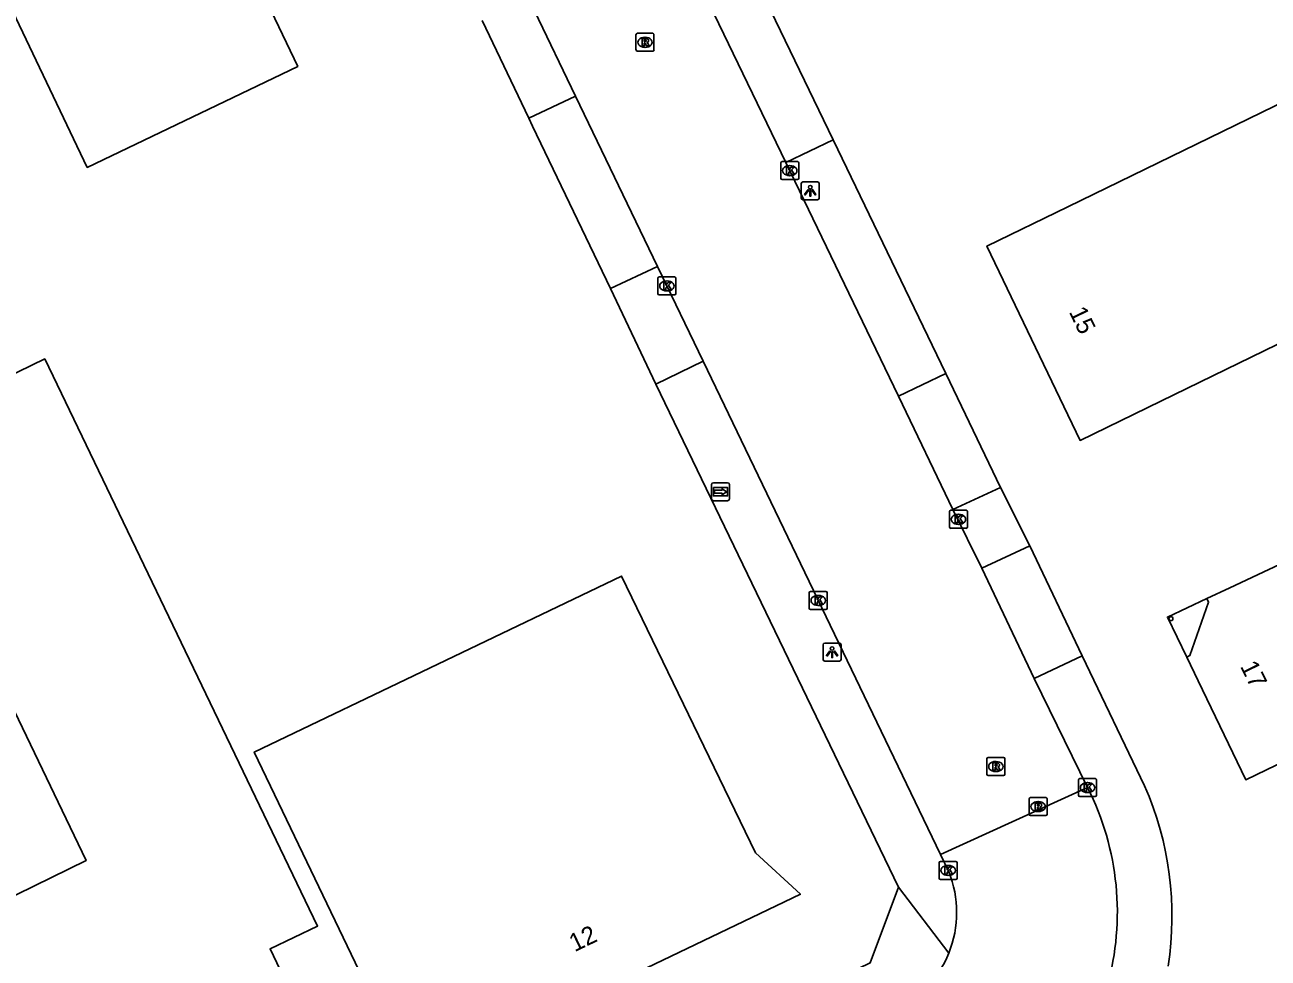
# Model space of a CAD drawing. Extents: x 157692 to 159670, y 381454 to 383289.
# Drawn here: x 158074.3 to 158143.4, y 381697.4 to 381749.2 of the extents above; entities that cross this region are included whole.
import ezdxf

# ---------------------------------------------------------------- set-up
doc = ezdxf.new("R2010")
doc.units = 0
for name, color, linetype in [('IMGEO_Kolk', 7, 'Continuous'), ('IMGEO_Lichtpunt', 7, 'Continuous'), ('IMGEO_Pand', 7, 'Continuous'), ('IMGEO_Pand_nummerreeks', 7, 'Continuous'), ('IMGEO_Pand_overbouw', 7, 'Continuous'), ('IMGEO_Rijbaan_lokaal_gesloten', 7, 'Continuous'), ('IMGEO_Rioolput', 7, 'Continuous'), ('IMGEO_Voetpad_open', 7, 'Continuous'), ('IMGEO_Wegwijzer', 7, 'Continuous')]:
    doc.layers.add(name, color=color, linetype=linetype)

msp = doc.modelspace()

# ---------------------------------------------------------------- linework, layer by layer
at = {"layer": 'IMGEO_Kolk'}
for p, q in [((158116.342, 381740.701), (158116.342, 381741.553)), ((158116.417, 381741.627), (158117.269, 381741.627)), ((158117.343, 381741.553), (158117.343, 381740.701)), ((158116.853, 381740.847), (158116.828, 381740.847)), ((158116.83, 381741.407), (158116.855, 381741.407)), ((158117.269, 381740.627), (158116.417, 381740.627)), ((158109.588, 381735.218), (158110.44, 381735.218)), ((158109.513, 381734.292), (158109.513, 381735.144)), ((158110.001, 381734.998), (158110.026, 381734.998)), ((158110.514, 381735.144), (158110.514, 381734.292)), ((158110.44, 381734.218), (158109.588, 381734.218)), ((158110.024, 381734.438), (158109.999, 381734.438)), ((158125.718, 381721.323), (158125.718, 381722.175)), ((158125.793, 381722.249), (158126.645, 381722.249)), ((158126.719, 381722.175), (158126.719, 381721.323)), ((158126.229, 381721.469), (158126.204, 381721.469)), ((158126.206, 381722.029), (158126.231, 381722.029)), ((158126.645, 381721.249), (158125.793, 381721.249)), ((158117.926, 381716.814), (158117.926, 381717.666)), ((158118.001, 381717.74), (158118.853, 381717.74)), ((158118.414, 381717.52), (158118.439, 381717.52)), ((158118.927, 381717.666), (158118.927, 381716.814)), ((158118.853, 381716.74), (158118.001, 381716.74)), ((158118.437, 381716.96), (158118.412, 381716.96)), ((158132.896, 381706.414), (158132.896, 381707.266)), ((158132.971, 381707.34), (158133.823, 381707.34)), ((158133.384, 381707.12), (158133.409, 381707.12)), ((158133.897, 381707.266), (158133.897, 381706.414)), ((158133.823, 381706.34), (158132.971, 381706.34)), ((158133.407, 381706.56), (158133.382, 381706.56)), ((158125.221, 381702.739), (158126.073, 381702.739)), ((158125.146, 381701.813), (158125.146, 381702.665)), ((158125.634, 381702.519), (158125.659, 381702.519)), ((158126.147, 381702.665), (158126.147, 381701.813)), ((158126.073, 381701.739), (158125.221, 381701.739)), ((158125.657, 381701.959), (158125.632, 381701.959))]:
    msp.add_line(p, q, dxfattribs=at)
for points in [[(158116.342, 381740.701), (158116.342, 381741.553)], [(158116.417, 381741.627), (158117.269, 381741.627)], [(158117.343, 381741.553), (158117.343, 381740.701)], [(158116.663, 381741.327), (158116.786, 381741.327), (158116.786, 381741.176), (158116.916, 381741.327), (158117.08, 381741.327), (158116.934, 381741.176), (158117.087, 381740.927), (158116.935, 381740.927), (158116.85, 381741.091), (158116.786, 381741.024), (158116.786, 381740.927), (158116.663, 381740.927), (158116.663, 381741.327)], [(158117.269, 381740.627), (158116.417, 381740.627)], [(158109.588, 381735.218), (158110.44, 381735.218)], [(158109.513, 381734.292), (158109.513, 381735.144)], [(158109.834, 381734.918), (158109.957, 381734.918), (158109.957, 381734.767), (158110.087, 381734.918), (158110.251, 381734.918), (158110.105, 381734.767), (158110.258, 381734.518), (158110.106, 381734.518), (158110.021, 381734.682), (158109.957, 381734.615), (158109.957, 381734.518), (158109.834, 381734.518), (158109.834, 381734.918)], [(158110.514, 381735.144), (158110.514, 381734.292)], [(158110.44, 381734.218), (158109.588, 381734.218)], [(158125.718, 381721.323), (158125.718, 381722.175)], [(158125.793, 381722.249), (158126.645, 381722.249)], [(158126.719, 381722.175), (158126.719, 381721.323)], [(158126.039, 381721.949), (158126.162, 381721.949), (158126.162, 381721.798), (158126.292, 381721.949), (158126.456, 381721.949), (158126.31, 381721.798), (158126.463, 381721.549), (158126.311, 381721.549), (158126.226, 381721.713), (158126.162, 381721.646), (158126.162, 381721.549), (158126.039, 381721.549), (158126.039, 381721.949)], [(158126.645, 381721.249), (158125.793, 381721.249)], [(158117.926, 381716.814), (158117.926, 381717.666)], [(158118.001, 381717.74), (158118.853, 381717.74)], [(158118.247, 381717.44), (158118.37, 381717.44), (158118.37, 381717.289), (158118.5, 381717.44), (158118.664, 381717.44), (158118.518, 381717.289), (158118.671, 381717.04), (158118.519, 381717.04), (158118.434, 381717.204), (158118.37, 381717.137), (158118.37, 381717.04), (158118.247, 381717.04), (158118.247, 381717.44)], [(158118.927, 381717.666), (158118.927, 381716.814)], [(158118.853, 381716.74), (158118.001, 381716.74)], [(158132.896, 381706.414), (158132.896, 381707.266)], [(158132.971, 381707.34), (158133.823, 381707.34)], [(158133.217, 381707.04), (158133.34, 381707.04), (158133.34, 381706.889), (158133.47, 381707.04), (158133.634, 381707.04), (158133.488, 381706.889), (158133.641, 381706.64), (158133.489, 381706.64), (158133.404, 381706.804), (158133.34, 381706.737), (158133.34, 381706.64), (158133.217, 381706.64), (158133.217, 381707.04)], [(158133.897, 381707.266), (158133.897, 381706.414)], [(158133.823, 381706.34), (158132.971, 381706.34)], [(158125.221, 381702.739), (158126.073, 381702.739)], [(158125.146, 381701.813), (158125.146, 381702.665)], [(158125.467, 381702.439), (158125.59, 381702.439), (158125.59, 381702.288), (158125.72, 381702.439), (158125.884, 381702.439), (158125.738, 381702.288), (158125.891, 381702.039), (158125.739, 381702.039), (158125.654, 381702.203), (158125.59, 381702.136), (158125.59, 381702.039), (158125.467, 381702.039), (158125.467, 381702.439)], [(158126.147, 381702.665), (158126.147, 381701.813)], [(158126.073, 381701.739), (158125.221, 381701.739)]]:
    msp.add_lwpolyline(points, dxfattribs=at)
for centre, start, end in [((158116.419, 381741.551), 91.55205, 178.44795), ((158116.419, 381741.551), 91.55205, 178.44795), ((158117.267, 381741.551), 1.55205, 88.44795), ((158117.267, 381741.551), 1.55205, 88.44795), ((158116.419, 381740.703), 181.55205, 268.44795), ((158116.419, 381740.703), 181.55205, 268.44795), ((158117.267, 381740.703), 271.55205, 358.44795), ((158117.267, 381740.703), 271.55205, 358.44795), ((158109.59, 381735.142), 91.55205, 178.44795), ((158109.59, 381735.142), 91.55205, 178.44795), ((158110.438, 381735.142), 1.55205, 88.44795), ((158110.438, 381735.142), 1.55205, 88.44795), ((158109.59, 381734.294), 181.55205, 268.44795), ((158109.59, 381734.294), 181.55205, 268.44795), ((158110.438, 381734.294), 271.55205, 358.44795), ((158110.438, 381734.294), 271.55205, 358.44795), ((158125.795, 381722.173), 91.55205, 178.44795), ((158125.795, 381722.173), 91.55205, 178.44795), ((158126.643, 381722.173), 1.55205, 88.44795), ((158126.643, 381722.173), 1.55205, 88.44795), ((158125.795, 381721.325), 181.55205, 268.44795), ((158125.795, 381721.325), 181.55205, 268.44795), ((158126.643, 381721.325), 271.55205, 358.44795), ((158126.643, 381721.325), 271.55205, 358.44795), ((158118.003, 381717.664), 91.55205, 178.44795), ((158118.003, 381717.664), 91.55205, 178.44795), ((158118.851, 381717.664), 1.55205, 88.44795), ((158118.851, 381717.664), 1.55205, 88.44795), ((158118.003, 381716.816), 181.55205, 268.44795), ((158118.003, 381716.816), 181.55205, 268.44795), ((158118.851, 381716.816), 271.55205, 358.44795), ((158118.851, 381716.816), 271.55205, 358.44795), ((158132.973, 381707.264), 91.55205, 178.44795), ((158132.973, 381707.264), 91.55205, 178.44795), ((158133.821, 381707.264), 1.55205, 88.44795), ((158133.821, 381707.264), 1.55205, 88.44795), ((158132.973, 381706.416), 181.55205, 268.44795), ((158132.973, 381706.416), 181.55205, 268.44795), ((158133.821, 381706.416), 271.55205, 358.44795), ((158133.821, 381706.416), 271.55205, 358.44795), ((158125.223, 381702.663), 91.55205, 178.44795), ((158125.223, 381702.663), 91.55205, 178.44795), ((158126.071, 381702.663), 1.55205, 88.44795), ((158126.071, 381702.663), 1.55205, 88.44795), ((158125.223, 381701.815), 181.55205, 268.44795), ((158125.223, 381701.815), 181.55205, 268.44795), ((158126.071, 381701.815), 271.55205, 358.44795), ((158126.071, 381701.815), 271.55205, 358.44795)]:
    msp.add_arc(centre, 0.0765, start, end, dxfattribs=at)
for centre, major_axis, ratio, start_param, end_param in [((158116.829, 381741.127), (-0.387, 0.002), 0.722429, 4.712389, 7.853982), ((158116.854, 381741.127), (-0.39, 0.002), 0.717154, 1.570796, 4.712389), ((158110, 381734.718), (-0.387, 0.002), 0.722429, 4.712389, 7.853982), ((158110.025, 381734.718), (-0.39, 0.002), 0.717154, 1.570796, 4.712389), ((158126.205, 381721.749), (-0.387, 0.002), 0.722429, 4.712389, 7.853982), ((158126.23, 381721.749), (-0.39, 0.002), 0.717154, 1.570796, 4.712389), ((158118.413, 381717.24), (-0.387, 0.002), 0.722429, 4.712389, 7.853982), ((158118.438, 381717.24), (-0.39, 0.002), 0.717154, 1.570796, 4.712389), ((158133.383, 381706.84), (-0.387, 0.002), 0.722429, 4.712389, 7.853982), ((158133.408, 381706.84), (-0.39, 0.002), 0.717154, 1.570796, 4.712389), ((158125.633, 381702.239), (-0.387, 0.002), 0.722429, 4.712389, 7.853982), ((158125.658, 381702.239), (-0.39, 0.002), 0.717154, 1.570796, 4.712389)]:
    msp.add_ellipse(centre, major_axis=major_axis, ratio=ratio, start_param=start_param, end_param=end_param, dxfattribs=at)
at = {"layer": 'IMGEO_Lichtpunt'}
for p, q in [((158117.483, 381740.407), (158117.483, 381739.6)), ((158117.483, 381740.407), (158117.483, 381739.6)), ((158118.385, 381740.502), (158117.577, 381740.502)), ((158118.385, 381740.502), (158117.577, 381740.502)), ((158118.479, 381739.6), (158118.479, 381740.407)), ((158118.479, 381739.6), (158118.479, 381740.407)), ((158117.577, 381739.506), (158118.385, 381739.506)), ((158117.577, 381739.506), (158118.385, 381739.506)), ((158118.698, 381714.775), (158118.698, 381713.968)), ((158118.698, 381714.775), (158118.698, 381713.968)), ((158119.6, 381714.87), (158118.792, 381714.87)), ((158119.6, 381714.87), (158118.792, 381714.87)), ((158119.694, 381713.968), (158119.694, 381714.775)), ((158119.694, 381713.968), (158119.694, 381714.775)), ((158118.792, 381713.874), (158119.6, 381713.874)), ((158118.792, 381713.874), (158119.6, 381713.874))]:
    msp.add_line(p, q, dxfattribs=at)
for points in [[(158117.857, 381740.071), (158117.896, 381740.043), (158117.708, 381739.781), (158117.67, 381739.808), (158117.857, 381740.071)], [(158118.069, 381740.043), (158118.107, 381740.07), (158118.294, 381739.808), (158118.255, 381739.78), (158118.069, 381740.043)], [(158117.959, 381740.023), (158118.006, 381740.023), (158118.006, 381739.701), (158117.959, 381739.701), (158117.959, 381740.023)], [(158119.072, 381714.439), (158119.111, 381714.411), (158118.923, 381714.149), (158118.885, 381714.176), (158119.072, 381714.439)], [(158119.174, 381714.391), (158119.221, 381714.391), (158119.221, 381714.069), (158119.174, 381714.069), (158119.174, 381714.391)], [(158119.284, 381714.411), (158119.322, 381714.438), (158119.509, 381714.176), (158119.47, 381714.148), (158119.284, 381714.411)]]:
    msp.add_lwpolyline(points, dxfattribs=at)
for centre in [(158117.982, 381740.205), (158119.197, 381714.573)]:
    msp.add_circle(centre, 0.0994, dxfattribs=at)
for centre, start, end in [((158117.577, 381740.407), 90, 180), ((158117.577, 381740.407), 90, 180), ((158118.385, 381740.407), 0, 90), ((158118.385, 381740.407), 0, 90), ((158117.577, 381739.6), 180, 270), ((158117.577, 381739.6), 180, 270), ((158118.385, 381739.6), 270, 0), ((158118.385, 381739.6), 270, 360), ((158118.792, 381714.775), 90, 180), ((158118.792, 381714.775), 90, 180), ((158119.6, 381714.775), 0, 90), ((158119.6, 381714.775), 0, 90), ((158118.792, 381713.968), 180, 270), ((158118.792, 381713.968), 180, 270), ((158119.6, 381713.968), 270, 0), ((158119.6, 381713.968), 270, 360)]:
    msp.add_arc(centre, 0.0946, start, end, dxfattribs=at)
at = {"layer": 'IMGEO_Pand'}
for points in [[(158073.628, 381750), (158077.795, 381741.308), (158089.492, 381746.916), (158088.009, 381750), (158076.855, 381773.194), (158075.215, 381772.432), (158073.743, 381775.528)], [(158162.359, 381748.983), (158165.723, 381742.068), (158155.454, 381737.077), (158137.477, 381728.32), (158132.981, 381726.13), (158127.801, 381736.932), (158132.298, 381739.12), (158150.219, 381747.837), (158152.092, 381743.988), (158162.359, 381748.983)], [(158151.951, 381730.299), (158166.876, 381737.497), (158174.051, 381722.618), (158146.716, 381709.452), (158142.191, 381707.273), (158139.542, 381712.78), (158138.914, 381714.086), (158139.078, 381714.178), (158140.124, 381717.153), (158140.027, 381717.345), (158141.314, 381717.95), (158150.29, 381722.166), (158147.447, 381728.127), (158151.951, 381730.299)], [(158082.315, 381685.049), (158082.781, 381686.285), (158085.446, 381687.641), (158086.722, 381687.201), (158086.823, 381687.022), (158090.172, 381688.615), (158091.103, 381691.273), (158087.956, 381697.889), (158090.593, 381699.145), (158075.432, 381730.662), (158070.933, 381728.483)], [(158066.42, 381726.297), (158077.722, 381702.786), (158067.138, 381697.606)], [(158095.837, 381690.555), (158117.435, 381700.917), (158114.941, 381703.211), (158107.496, 381718.594), (158087.076, 381708.818), (158095.837, 381690.555)]]:
    msp.add_lwpolyline(points, dxfattribs=at)
for start, end in [(0, 180), (180, 0)]:
    msp.add_arc((158138.034, 381716.229), 0.11, start, end, dxfattribs=at)
at = {"layer": 'IMGEO_Pand_overbouw'}
msp.add_lwpolyline([(158138.914, 381714.086), (158139.078, 381714.178), (158140.124, 381717.153), (158140.027, 381717.345), (158137.84, 381716.318)], close=True, dxfattribs=at)
at = {"layer": 'IMGEO_Rijbaan_lokaal_gesloten'}
for points in [[(158109.618, 381756.099), (158112.566, 381750), (158112.648, 381749.831), (158116.624, 381741.577)], [(158104.936, 381745.273), (158102.661, 381750), (158102.332, 381750.683)], [(158109.491, 381735.808), (158104.936, 381745.273)], [(158116.624, 381741.577), (158122.883, 381728.587)], [(158112.026, 381730.541), (158109.491, 381735.808)], [(158125.222, 381703.122), (158112.026, 381730.541)], [(158122.883, 381728.587), (158125.912, 381722.3)], [(158125.912, 381722.3), (158127.521, 381719.041)], [(158127.521, 381719.041), (158130.435, 381712.908)], [(158130.435, 381712.908), (158133.396, 381706.839)], [(158125.222, 381703.122), (158133.396, 381706.839)], [(158125.682, 381702.167), (158125.222, 381703.122)]]:
    msp.add_lwpolyline(points, dxfattribs=at)
for centre, radius, start, end in [((158119.761, 381699.915), 15.292, 344.37372, 26.92108), ((158120.059, 381699.905), 6.061, 338.05954, 21.91515), ((158120.059, 381699.901), 6.06, 294.23298, 338.09434)]:
    msp.add_arc(centre, radius, start, end, dxfattribs=at)
at = {"layer": 'IMGEO_Rioolput'}
for p, q in [((158108.295, 381747.831), (158108.295, 381748.683)), ((158108.37, 381748.757), (158109.222, 381748.757)), ((158108.783, 381748.537), (158108.808, 381748.537)), ((158109.296, 381748.683), (158109.296, 381747.831)), ((158109.222, 381747.757), (158108.37, 381747.757)), ((158108.806, 381747.977), (158108.781, 381747.977)), ((158127.801, 381707.586), (158127.801, 381708.438)), ((158127.876, 381708.512), (158128.728, 381708.512)), ((158128.289, 381708.292), (158128.314, 381708.292)), ((158128.802, 381708.438), (158128.802, 381707.586)), ((158128.312, 381707.732), (158128.287, 381707.732)), ((158128.728, 381707.512), (158127.876, 381707.512)), ((158130.15, 381705.358), (158130.15, 381706.21)), ((158130.225, 381706.284), (158131.077, 381706.284)), ((158131.151, 381706.21), (158131.151, 381705.358)), ((158130.661, 381705.504), (158130.636, 381705.504)), ((158130.638, 381706.064), (158130.663, 381706.064)), ((158131.077, 381705.284), (158130.225, 381705.284))]:
    msp.add_line(p, q, dxfattribs=at)
for points in [[(158108.295, 381747.831), (158108.295, 381748.683)], [(158108.37, 381748.757), (158109.222, 381748.757)], [(158108.884, 381748.455), (158108.632, 381748.457), (158108.632, 381748.057)], [(158108.81, 381748.376), (158108.756, 381748.376), (158108.756, 381748.295)], [(158109.296, 381748.683), (158109.296, 381747.831)], [(158109.222, 381747.757), (158108.37, 381747.757)], [(158108.632, 381748.057), (158108.756, 381748.057), (158108.756, 381748.219), (158108.767, 381748.219)], [(158108.756, 381748.295), (158108.808, 381748.295)], [(158108.814, 381748.19), (158108.885, 381748.057), (158109.025, 381748.057), (158108.96, 381748.183)], [(158127.801, 381707.586), (158127.801, 381708.438)], [(158127.876, 381708.512), (158128.728, 381708.512)], [(158128.802, 381708.438), (158128.802, 381707.586)], [(158128.39, 381708.21), (158128.138, 381708.212), (158128.138, 381707.812)], [(158128.138, 381707.812), (158128.262, 381707.812), (158128.262, 381707.974), (158128.273, 381707.974)], [(158128.316, 381708.131), (158128.262, 381708.131), (158128.262, 381708.05)], [(158128.262, 381708.05), (158128.314, 381708.05)], [(158128.32, 381707.945), (158128.391, 381707.812), (158128.531, 381707.812), (158128.466, 381707.938)], [(158128.728, 381707.512), (158127.876, 381707.512)], [(158130.15, 381705.358), (158130.15, 381706.21)], [(158130.225, 381706.284), (158131.077, 381706.284)], [(158131.151, 381706.21), (158131.151, 381705.358)], [(158130.739, 381705.982), (158130.487, 381705.984), (158130.487, 381705.584)], [(158130.487, 381705.584), (158130.611, 381705.584), (158130.611, 381705.746), (158130.622, 381705.746)], [(158130.665, 381705.903), (158130.611, 381705.903), (158130.611, 381705.822)], [(158130.611, 381705.822), (158130.663, 381705.822)], [(158130.669, 381705.717), (158130.74, 381705.584), (158130.88, 381705.584), (158130.815, 381705.71)], [(158131.077, 381705.284), (158130.225, 381705.284)]]:
    msp.add_lwpolyline(points, dxfattribs=at)
for centre, radius, start, end in [((158108.372, 381748.681), 0.0765, 91.55205, 178.44795), ((158108.372, 381748.681), 0.0765, 91.55205, 178.44795), ((158108.816, 381748.28), 0.0964, 77.00612, 93.18647), ((158108.83, 381748.337), 0.0378, 276.66336, 79.67722), ((158108.883, 381748.345), 0.109, 350.36119, 89.41601), ((158108.881, 381748.345), 0.112, 277.58423, 350.98172), ((158109.22, 381748.681), 0.0765, 1.55205, 88.44795), ((158109.22, 381748.681), 0.0765, 1.55205, 88.44795), ((158108.372, 381747.833), 0.0765, 181.55205, 268.44795), ((158108.372, 381747.833), 0.0765, 181.55205, 268.44795), ((158108.766, 381748.166), 0.0533, 26.02933, 88.69889), ((158108.792, 381748.484), 0.19, 274.7715, 282.96867), ((158108.865, 381748.13), 0.108, 29.51342, 73.79051), ((158109.22, 381747.833), 0.0765, 271.55205, 358.44795), ((158109.22, 381747.833), 0.0765, 271.55205, 358.44795), ((158127.878, 381708.436), 0.0765, 91.55205, 178.44795), ((158127.878, 381708.436), 0.0765, 91.55205, 178.44795), ((158128.726, 381708.436), 0.0765, 1.55205, 88.44795), ((158128.726, 381708.436), 0.0765, 1.55205, 88.44795), ((158127.878, 381707.588), 0.0765, 181.55205, 268.44795), ((158127.878, 381707.588), 0.0765, 181.55205, 268.44795), ((158128.272, 381707.921), 0.0533, 26.02933, 88.69889), ((158128.298, 381708.239), 0.19, 274.7715, 282.96867), ((158128.322, 381708.035), 0.0964, 77.00612, 93.18647), ((158128.336, 381708.092), 0.0378, 276.66336, 79.67722), ((158128.389, 381708.1), 0.109, 350.36119, 89.41601), ((158128.387, 381708.1), 0.112, 277.58423, 350.98172), ((158128.371, 381707.885), 0.108, 29.51342, 73.79051), ((158128.726, 381707.588), 0.0765, 271.55205, 358.44795), ((158128.726, 381707.588), 0.0765, 271.55205, 358.44795), ((158130.227, 381706.208), 0.0765, 91.55205, 178.44795), ((158130.227, 381706.208), 0.0765, 91.55205, 178.44795), ((158131.075, 381706.208), 0.0765, 1.55205, 88.44795), ((158131.075, 381706.208), 0.0765, 1.55205, 88.44795), ((158130.621, 381705.693), 0.0533, 26.02933, 88.69889), ((158130.647, 381706.011), 0.19, 274.7715, 282.96867), ((158130.671, 381705.807), 0.0964, 77.00612, 93.18647), ((158130.685, 381705.864), 0.0378, 276.66336, 79.67722), ((158130.738, 381705.872), 0.109, 350.36119, 89.41601), ((158130.736, 381705.872), 0.112, 277.58423, 350.98172), ((158130.72, 381705.657), 0.108, 29.51342, 73.79051), ((158130.227, 381705.36), 0.0765, 181.55205, 268.44795), ((158130.227, 381705.36), 0.0765, 181.55205, 268.44795), ((158131.075, 381705.36), 0.0765, 271.55205, 358.44795), ((158131.075, 381705.36), 0.0765, 271.55205, 358.44795)]:
    msp.add_arc(centre, radius, start, end, dxfattribs=at)
for centre, major_axis, ratio, start_param, end_param in [((158108.782, 381748.257), (-0.387, 0.002), 0.722429, 4.712389, 7.853982), ((158108.807, 381748.257), (-0.39, 0.002), 0.717154, 1.570796, 4.712389), ((158128.288, 381708.012), (-0.387, 0.002), 0.722429, 4.712389, 7.853982), ((158128.313, 381708.012), (-0.39, 0.002), 0.717154, 1.570796, 4.712389), ((158130.637, 381705.784), (-0.387, 0.002), 0.722429, 4.712389, 7.853982), ((158130.662, 381705.784), (-0.39, 0.002), 0.717154, 1.570796, 4.712389)]:
    msp.add_ellipse(centre, major_axis=major_axis, ratio=ratio, start_param=start_param, end_param=end_param, dxfattribs=at)
at = {"layer": 'IMGEO_Voetpad_open'}
for points in [[(158112.225, 381757.328), (158115.269, 381751.09), (158115.795, 381750), (158119.248, 381742.84)], [(158099.751, 381749.471), (158102.331, 381744.049)], [(158102.331, 381744.049), (158104.936, 381745.273)], [(158102.331, 381744.049), (158102.545, 381743.606), (158106.88, 381734.578)], [(158116.624, 381741.577), (158119.248, 381742.84)], [(158119.248, 381742.84), (158125.511, 381729.855)], [(158109.491, 381735.808), (158106.88, 381734.578)], [(158106.88, 381734.578), (158109.399, 381729.267)], [(158112.026, 381730.541), (158109.399, 381729.267)], [(158125.511, 381729.855), (158122.883, 381728.587)], [(158125.511, 381729.855), (158128.564, 381723.514)], [(158109.399, 381729.267), (158122.884, 381701.311)], [(158125.912, 381722.3), (158128.564, 381723.514)], [(158128.564, 381723.514), (158130.19, 381720.284)], [(158130.19, 381720.284), (158127.521, 381719.041)], [(158130.19, 381720.284), (158133.095, 381714.162)], [(158130.435, 381712.908), (158133.095, 381714.162)], [(158133.095, 381714.162), (158136.569, 381706.935)], [(158122.884, 381701.311), (158121.318, 381697.1), (158107.373, 381690.341), (158095.213, 381684.451), (158075.377, 381674.875)], [(158122.884, 381701.311), (158125.681, 381697.64)]]:
    msp.add_lwpolyline(points, dxfattribs=at)
msp.add_arc((158120.126, 381699.695), 17.966, 351.12057, 23.76426, dxfattribs=at)
at = {"layer": 'IMGEO_Wegwijzer'}
for p, q in [((158112.5, 381722.882), (158112.5, 381723.682)), ((158112.5, 381723.682), (158112.5, 381722.882)), ((158112.6, 381723.782), (158113.39, 381723.782)), ((158113.39, 381723.782), (158112.6, 381723.782)), ((158113.49, 381723.682), (158113.49, 381722.882)), ((158113.49, 381722.882), (158113.49, 381723.682)), ((158113.39, 381722.782), (158112.6, 381722.782)), ((158112.6, 381722.782), (158113.39, 381722.782))]:
    msp.add_line(p, q, dxfattribs=at)
for points in [[(158112.601, 381723.514), (158113.389, 381723.514), (158113.389, 381723.05), (158112.601, 381723.05), (158112.601, 381723.514)], [(158112.666, 381723.366), (158112.666, 381723.282), (158112.666, 381723.198), (158113.077, 381723.198), (158113.077, 381723.115), (158113.324, 381723.282), (158113.077, 381723.449), (158113.077, 381723.366), (158112.666, 381723.366)]]:
    msp.add_lwpolyline(points, dxfattribs=at)
for centre, start, end in [((158112.6, 381723.682), 90, 180), ((158112.6, 381723.682), 90, 180), ((158113.39, 381723.682), 0, 90), ((158113.39, 381723.682), 360, 90), ((158112.6, 381722.882), 180, 270), ((158112.6, 381722.882), 180, 270), ((158113.39, 381722.882), 270, 0), ((158113.39, 381722.882), 270, 0)]:
    msp.add_arc(centre, 0.1, start, end, dxfattribs=at)

# ---------------------------------------------------------------- texts
at = {"layer": 'IMGEO_Pand_nummerreeks'}
for s, rotation, p in [('15', 295.62246, (158132.346, 381733.284)), ('17', 296.49927, (158141.859, 381713.587)), ('12', 25.63014, (158104.881, 381697.689))]:
    msp.add_text(s, height=1, rotation=rotation, dxfattribs=at).set_placement(p)

doc.saveas('drawing.dxf')
